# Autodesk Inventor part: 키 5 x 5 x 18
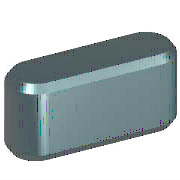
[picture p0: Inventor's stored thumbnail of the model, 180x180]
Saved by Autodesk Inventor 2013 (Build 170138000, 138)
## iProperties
IsCustomPart: 1
Created: 2012-02
Part Number: 키 5 x 5 x 18
Material: 강철, 연강
Description: 키 및 해당 키홈
Document SubType Name: Modeling
Standard: KS B 1311
Designer: mduedu
Standards Organization: KS
Language: ko-KR
Size Designation: 5 x 5 x 18
Categories: <MemberInstance><Categories><Category DisplayName="샤프트 부품" InternalName="7f7aeb1f-a693-4053-b835-cee3144e0d98" Mnemonic="SHFT"><Category DisplayName="키" Interna
Density: 7.86 g/cm^3
Mass: 3.27476 g
Surface Area: 3.57848 cm^2
Volume: 0.416636 cm^3
Author: mduedu
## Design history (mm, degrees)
workplane "Work Plane1"
workplane "Work Plane2"
sketch "스케치1"
  geometry: L1 (2.5, 2.5)-(15.5, 2.5); L2 (15.5, -2.5)-(2.5, -2.5); L3 (0, 9.4)-(0, -7.4) reference; L4 (-5, 0)-(30, 0) reference; L5 (18, 0)-(18, 7); A1 r 2.5 centre (2.5, 0) between (2.5, 2.5) and (2.5, -2.5); A2 r 2.5 centre (15.5, 0) between (15.5, -2.5) and (15.5, 2.5)
  constraints: 6 end point, 5 point on circle, 4 tangent, 3 point on line, 2 centre point, 1 horizontal, 1 parallel, 1 perpendicular
  dimensions: "d0" = 2.5 radius of A1 (= 0.5 x PB); "d13" = 2.5 radius of A2 (= 0.5 x PB); "d14" = 18 distance between parallel lines of L5 L3 (= NLG)
extrude "본체1" new body sketch "스케치1" taper "d3" = 0 deg; stored distance "d4" = 10
workplane "Work Plane3"
body "Solid1"
chamfer "모따기1" distance "d8" = 0.4 (= PHH); stored, may be unused: second distance "d9" = 0.4 (= PHH), angle "d15" = 45 deg
other parameters: "d1" = -3 (= -PNT), "d2" = 2 (= PH - PNT), "NLG" = 18 [user parameter; used in 3 equation terms], "PB" = 5 [user parameter; used in 2 equation terms], "PNT" = 3 [user parameter; used in 2 equation terms], "PH" = 5 [user parameter; used in 1 equation term], "PHH" = 0.4 [user parameter; used in 2 equation terms], "d10" = 0, "d16" = 0, "d17" = 0, "d18" = 0, "WDMIN" = 12 [user parameter], "PLB2" = 18 (= NLG) [user parameter], "WDMAX" = 17 [user parameter], "PLB1" = 18 (= NLG) [user parameter], "RR" = 0.16 [user parameter], "PUEB" = 2.3 [user parameter]
